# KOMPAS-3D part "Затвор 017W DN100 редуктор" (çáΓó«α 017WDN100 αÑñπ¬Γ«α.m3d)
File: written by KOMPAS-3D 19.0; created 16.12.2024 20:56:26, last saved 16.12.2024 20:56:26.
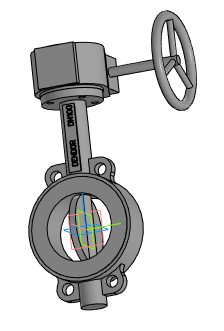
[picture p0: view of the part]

Document properties: Автор: Евгений; Полное имя файла: ..\Затвор 017WDN100 редуктор.a3d

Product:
- Part/product: Затвор 017W DN100 редуктор
    Масса: 14.0138

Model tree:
1. Операция без истории:1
